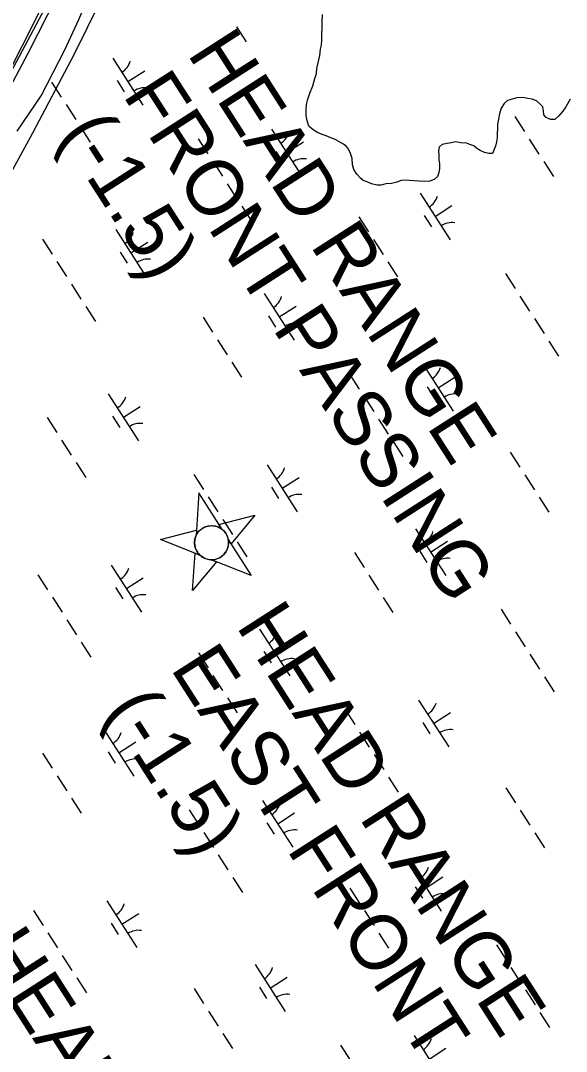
# Model space of a CAD drawing. Extents: x 3937982 to 3958556, y 219448 to 241894.
# Drawn here: x 3943922 to 3944412, y 234922 to 235847 of the extents above; entities that cross this region are included whole.
import ezdxf

# ---------------------------------------------------------------- set-up
doc = ezdxf.new("R2010")
doc.units = 0
for name, color, linetype in [('V-CHAN-NAID', 7, 'Continuous'), ('V-RIVR-EDGE', 7, 'Continuous'), ('V-RIVR-JETY', 7, 'Continuous'), ('V-RRAP-FSHR', 7, 'Continuous'), ('V-TOPO-SHOR', 7, 'Continuous'), ('V-WETL-SWMP', 7, 'Continuous')]:
    doc.layers.add(name, color=color, linetype=linetype)

msp = doc.modelspace()

# ---------------------------------------------------------------- linework, layer by layer
at = {"layer": 'V-CHAN-NAID'}
for points in [[(3944102.509, 235391.101), (3944082.065, 235423.425), (3944079.606, 235385.257), (3944080.108, 235386.241), (3944080.574, 235387.022), (3944081.179, 235387.901), (3944081.855, 235388.749), (3944082.313, 235389.26), (3944082.899, 235389.851), (3944083.441, 235390.344), (3944084.062, 235390.855), (3944084.763, 235391.37), (3944085.425, 235391.802), (3944086.326, 235392.318), (3944087.057, 235392.678), (3944088.089, 235393.109), (3944089.028, 235393.426), (3944089.985, 235393.682), (3944090.868, 235393.861), (3944091.733, 235393.984), (3944092.598, 235394.056), (3944093.616, 235394.079), (3944094.513, 235394.043), (3944095.317, 235393.965), (3944096.07, 235393.853), (3944096.986, 235393.664), (3944097.676, 235393.483), (3944098.728, 235393.138), (3944099.421, 235392.863), (3944100.327, 235392.443), (3944101.193, 235391.97), (3944101.871, 235391.547)], [(3944102.509, 235391.101), (3944099.947, 235395.152), (3944132.362, 235403.422), (3944110.999, 235377.678), (3944108.436, 235381.73), (3944108.253, 235382.549), (3944107.948, 235383.598), (3944107.586, 235384.578), (3944107.166, 235385.518), (3944106.898, 235386.04), (3944106.518, 235386.707), (3944106.052, 235387.431), (3944105.652, 235387.988), (3944105.052, 235388.736), (3944104.591, 235389.251), (3944103.947, 235389.898), (3944103.357, 235390.428), (3944102.939, 235390.772)], [(3944083.039, 235367.637), (3944047.499, 235381.771), (3944079.914, 235390.041), (3944079.606, 235385.257), (3944079.372, 235384.729), (3944078.963, 235383.645), (3944078.696, 235382.752), (3944078.46, 235381.729), (3944078.309, 235380.807), (3944078.215, 235379.883), (3944078.179, 235379.026), (3944078.197, 235378.04), (3944078.277, 235377.073), (3944078.42, 235376.1), (3944078.577, 235375.342), (3944078.794, 235374.514), (3944079.158, 235373.425), (3944079.452, 235372.703), (3944079.891, 235371.782), (3944080.263, 235371.107), (3944080.756, 235370.318), (3944081.246, 235369.629), (3944081.782, 235368.957), (3944082.427, 235368.241)], [(3944108.436, 235381.73), (3944128.88, 235349.405), (3944093.341, 235363.54), (3944094.213, 235363.559), (3944095.255, 235363.647), (3944096.115, 235363.774), (3944097.137, 235363.992), (3944098.035, 235364.245), (3944098.832, 235364.52), (3944099.775, 235364.912), (3944100.487, 235365.259), (3944101.449, 235365.803), (3944102.308, 235366.372), (3944103.191, 235367.052), (3944103.859, 235367.639), (3944104.665, 235368.448), (3944105.392, 235369.296), (3944106.023, 235370.147), (3944106.455, 235370.81), (3944106.989, 235371.751), (3944107.426, 235372.663), (3944107.814, 235373.634), (3944108.121, 235374.58), (3944108.352, 235375.484), (3944108.555, 235376.585), (3944108.678, 235377.7), (3944108.718, 235378.726), (3944108.685, 235379.826), (3944108.607, 235380.651)], [(3944093.341, 235363.54), (3944097.795, 235361.768), (3944076.432, 235336.025), (3944078.584, 235369.409), (3944083.039, 235367.637), (3944083.689, 235367.065), (3944084.36, 235366.538), (3944085.328, 235365.877), (3944086.169, 235365.386), (3944087.142, 235364.902), (3944088.122, 235364.498), (3944089.065, 235364.182), (3944089.904, 235363.956), (3944090.875, 235363.758), (3944091.79, 235363.63), (3944092.712, 235363.557)]]:
    msp.add_lwpolyline(points, close=True, dxfattribs=at)
msp.add_circle((3944093.448, 235378.81), 15.27, dxfattribs=at)
at = {"layer": 'V-RIVR-EDGE'}
msp.add_lwpolyline([(3944193.63, 236392.457), (3944193.155, 236391.169), (3944172.689, 236343.94), (3944119.949, 236234.524), (3944097.121, 236194.379), (3944079.017, 236141.639), (3944066.422, 236128.257), (3944040.446, 236067.646), (3944007.385, 235995.227), (3943991.642, 235945.636), (3943960.942, 235890.535), (3943855.463, 235692.957), (3943812.956, 235631.558), (3943768.875, 235583.541), (3943727.155, 235505.612), (3943670.48, 235374.156), (3943636.632, 235260.018), (3943585.466, 235124.626), (3943579.956, 235075.035), (3943597.274, 234983.724), (3943619.314, 234871.947)], dxfattribs=at)
at = {"layer": 'V-RIVR-JETY'}
for points in [[(3943918.966, 235747.869), (3943940.493, 235779.634), (3943961.753, 235820.78), (3943974.23, 235847.974), (3943989.155, 235882.951), (3944009.623, 235923.326), (3944029.298, 235962.932), (3944042.598, 235993.238), (3944058.298, 236027.817), (3944072.734, 236055.375), (3944088.858, 236092.29), (3944101.007, 236124.177), (3944109.06, 236142.048), (3944128.278, 236176.577), (3944154.126, 236239.551), (3944186.216, 236301.659), (3944206.653, 236339.69), (3944222.709, 236371.526), (3944236.476, 236407.692), (3944242.031, 236423.901)], [(3944205.869, 236400.408), (3944194.979, 236373.066), (3944180.859, 236339.641), (3944150.089, 236288.851), (3944127.236, 236245.38), (3944097.892, 236184.016), (3944079.325, 236139.707), (3944064.786, 236104.334), (3944042.604, 236052.647), (3944009.232, 235982.349), (3943954.976, 235869.723), (3943928.492, 235817.704), (3943901.241, 235766.865)]]:
    msp.add_lwpolyline(points, dxfattribs=at)
at = {"layer": 'V-RRAP-FSHR'}
msp.add_lwpolyline([(3943648.444, 234864.923), (3943633.272, 234943.444), (3943617.876, 235021.948), (3943622.994, 235100.327), (3943650.171, 235175.566), (3943678.906, 235250.224), (3943708.387, 235324.593), (3943738.82, 235398.878), (3943769.606, 235472.399), (3943805.37, 235543.862), (3943853.205, 235607.915), (3943894.849, 235676.646), (3943933.18, 235746.524), (3943970.3, 235817.305), (3944005.82, 235888.983), (3944041.119, 235960.773), (3944076.417, 236032.566), (3944110.874, 236104.758), (3944144.447, 236177.374), (3944176.138, 236250.819), (3944207.167, 236324.555), (3944236.607, 236398.941), (3944248.265, 236427.951)], dxfattribs=at)
at = {"layer": 'V-TOPO-SHOR'}
for points in [[(3944236.925, 235700.745), (3944233.793, 235702.185), (3944229.615, 235703.641), (3944227.195, 235705.773), (3944223.744, 235709.316), (3944220.999, 235713.551), (3944220.006, 235717.762), (3944219.732, 235723.363), (3944218.042, 235727.934), (3944216.344, 235731.805), (3944214.628, 235734.277), (3944211.857, 235736.413), (3944209.078, 235737.849), (3944204.214, 235740.363), (3944200.382, 235741.813), (3944196.208, 235743.618), (3944192.731, 235745.064), (3944188.555, 235746.868), (3944185.43, 235748.658), (3944183.005, 235750.44), (3944180.584, 235752.572), (3944179.245, 235757.137), (3944178.262, 235762.048), (3944178.321, 235766.596), (3944178.741, 235771.837), (3944179.855, 235776.722), (3944181.674, 235781.944), (3944184.209, 235788.559), (3944186.046, 235795.182), (3944187.506, 235799.71), (3944187.918, 235804.253), (3944189.767, 235811.927), (3944190.519, 235815.765), (3944191.291, 235821.352), (3944192.043, 235825.19), (3944192.452, 235829.732), (3944192.51, 235833.93), (3944192.598, 235840.576), (3944192.665, 235845.823), (3944193.104, 235852.465)], [(3944415.312, 235776.748), (3944411.369, 235769.803), (3944408.52, 235765.992), (3944404.967, 235761.841), (3944401.424, 235758.39), (3944397.576, 235758.439), (3944393.75, 235760.239), (3944391.684, 235762.717), (3944391.381, 235766.219), (3944390.727, 235769.728), (3944388.313, 235772.208), (3944384.852, 235775.053), (3944381.022, 235776.502), (3944377.184, 235777.252), (3944372.646, 235778.014), (3944367.392, 235777.733), (3944363.182, 235776.738), (3944358.967, 235775.397), (3944356.13, 235772.634), (3944353.276, 235768.474), (3944351.811, 235763.596), (3944351.047, 235758.707), (3944349.937, 235754.173), (3944349.89, 235750.675), (3944349.816, 235745.08), (3944349.776, 235741.93), (3944349.028, 235738.442), (3944348.278, 235734.605), (3944346.828, 235730.775), (3944345.393, 235727.996), (3944342.245, 235728.037), (3944338.405, 235728.786), (3944334.581, 235730.586), (3944331.11, 235732.733), (3944328.689, 235734.865), (3944325.206, 235735.958), (3944322.072, 235737.05), (3944317.18, 235737.466), (3944312.641, 235738.225), (3944308.435, 235737.58), (3944304.926, 235736.929), (3944300.365, 235735.94), (3944297.535, 235733.527), (3944297.144, 235730.384), (3944297.443, 235726.531), (3944297.382, 235721.985), (3944298.039, 235718.827), (3944297.98, 235714.278), (3944297.232, 235710.79), (3944296.136, 235707.307), (3944293.302, 235704.546), (3944289.435, 235703.196), (3944284.534, 235702.912), (3944279.287, 235702.981), (3944275.093, 235703.387), (3944270.901, 235703.792), (3944267.403, 235703.839), (3944263.551, 235703.54), (3944259.684, 235702.193), (3944254.769, 235700.858), (3944249.868, 235700.573), (3944245.655, 235699.58), (3944242.157, 235699.627), (3944236.925, 235700.745)]]:
    msp.add_lwpolyline(points, dxfattribs=at)
at = {"layer": 'V-WETL-SWMP'}
for p, q in [((3943962.314, 235901.421), (3943897.877, 235774.016)), ((3944192.453, 235829.733), (3944192.666, 235845.824)), ((3944192.666, 235845.824), (3944193.104, 235852.465)), ((3944115.772, 235841.666), (3944124.432, 235828.212)), ((3944192.043, 235825.19), (3944192.453, 235829.733)), ((3944190.518, 235815.764), (3944191.292, 235821.352)), ((3944191.292, 235821.352), (3944192.043, 235825.19)), ((3944004.791, 235813.395), (3944031.853, 235771.352)), ((3944187.917, 235804.253), (3944189.768, 235811.926)), ((3944189.768, 235811.926), (3944190.518, 235815.764)), ((3944018.322, 235792.374), (3944033.458, 235802.116)), ((3944186.047, 235795.182), (3944187.507, 235799.71)), ((3944187.507, 235799.71), (3944187.917, 235804.253)), ((3943949.925, 235791.998), (3943958.585, 235778.544)), ((3944008.587, 235793.243), (3944015.082, 235783.152)), ((3944184.21, 235788.559), (3944186.047, 235795.182)), ((3944179.855, 235776.721), (3944181.673, 235781.945)), ((3944181.673, 235781.945), (3944184.21, 235788.559)), ((3943962.915, 235771.817), (3943971.575, 235758.363)), ((3944178.321, 235766.596), (3944178.74, 235771.838)), ((3944178.74, 235771.838), (3944179.855, 235776.721)), ((3944356.13, 235772.634), (3944353.276, 235768.474)), ((3944358.966, 235775.396), (3944356.13, 235772.634)), ((3944363.182, 235776.739), (3944358.966, 235775.396)), ((3944367.393, 235777.733), (3944363.182, 235776.739)), ((3944372.645, 235778.013), (3944367.393, 235777.733)), ((3944377.183, 235777.253), (3944372.645, 235778.013)), ((3944381.021, 235776.503), (3944377.183, 235777.253)), ((3944384.851, 235775.052), (3944381.021, 235776.503)), ((3944388.312, 235772.208), (3944384.851, 235775.052)), ((3944390.728, 235769.727), (3944388.312, 235772.208)), ((3944415.311, 235776.748), (3944411.37, 235769.803)), ((3944178.261, 235762.048), (3944178.321, 235766.596)), ((3944179.245, 235757.137), (3944178.261, 235762.048)), ((3944351.812, 235763.595), (3944351.047, 235758.707)), ((3944353.276, 235768.474), (3944351.812, 235763.595)), ((3944391.381, 235766.219), (3944390.728, 235769.727)), ((3944391.684, 235762.717), (3944391.381, 235766.219)), ((3944393.751, 235760.24), (3944391.684, 235762.717)), ((3944404.967, 235761.841), (3944401.423, 235758.389)), ((3944408.521, 235765.992), (3944404.967, 235761.841)), ((3944411.37, 235769.803), (3944408.521, 235765.992)), ((3944180.584, 235752.571), (3944179.245, 235757.137)), ((3944183.005, 235750.44), (3944180.584, 235752.571)), ((3944349.938, 235754.174), (3944349.775, 235741.931)), ((3944351.047, 235758.707), (3944349.938, 235754.174)), ((3944365.487, 235761.039), (3944374.147, 235747.585)), ((3944397.575, 235758.44), (3944393.751, 235760.24)), ((3944401.423, 235758.389), (3944397.575, 235758.44)), ((3943975.905, 235751.637), (3943984.564, 235738.183)), ((3944147.357, 235749.705), (3944174.419, 235707.662)), ((3944185.43, 235748.658), (3944183.005, 235750.44)), ((3944188.555, 235746.868), (3944185.43, 235748.658)), ((3944192.73, 235745.063), (3944188.555, 235746.868)), ((3944196.209, 235743.617), (3944192.73, 235745.063)), ((3944200.383, 235741.813), (3944196.209, 235743.617)), ((3944081.492, 235741.11), (3944090.152, 235727.656)), ((3944160.888, 235728.683), (3944176.023, 235738.426)), ((3944204.213, 235740.363), (3944200.383, 235741.813)), ((3944211.857, 235736.413), (3944204.213, 235740.363)), ((3944214.628, 235734.277), (3944211.857, 235736.413)), ((3944216.344, 235731.805), (3944214.628, 235734.277)), ((3944300.366, 235735.939), (3944297.535, 235733.527)), ((3944304.927, 235736.928), (3944300.366, 235735.939)), ((3944308.434, 235737.581), (3944304.927, 235736.928)), ((3944312.641, 235738.225), (3944308.434, 235737.581)), ((3944317.179, 235737.465), (3944312.641, 235738.225)), ((3944322.072, 235737.05), (3944317.179, 235737.465)), ((3944325.206, 235735.959), (3944322.072, 235737.05)), ((3944328.69, 235734.864), (3944325.206, 235735.959)), ((3944331.111, 235732.732), (3944328.69, 235734.864)), ((3944348.279, 235734.604), (3944346.828, 235730.775)), ((3944349.029, 235738.442), (3944348.279, 235734.604)), ((3944349.775, 235741.931), (3944349.029, 235738.442)), ((3944378.477, 235740.858), (3944387.137, 235727.404)), ((3944151.153, 235729.553), (3944157.648, 235719.462)), ((3944218.042, 235727.934), (3944216.344, 235731.805)), ((3944219.731, 235723.364), (3944218.042, 235727.934)), ((3944297.535, 235733.527), (3944297.143, 235730.384)), ((3944297.143, 235730.384), (3944297.442, 235726.531)), ((3944297.442, 235726.531), (3944297.382, 235721.984)), ((3944334.581, 235730.587), (3944331.111, 235732.732)), ((3944338.405, 235728.787), (3944334.581, 235730.587)), ((3944342.244, 235728.036), (3944338.405, 235728.787)), ((3944345.392, 235727.995), (3944342.244, 235728.036)), ((3944346.828, 235730.775), (3944345.392, 235727.995)), ((3944094.482, 235720.929), (3944103.142, 235707.475)), ((3944220.007, 235717.762), (3944219.731, 235723.364)), ((3944221, 235713.551), (3944220.007, 235717.762)), ((3944297.382, 235721.984), (3944298.039, 235718.827)), ((3944298.039, 235718.827), (3944297.979, 235714.279)), ((3944391.467, 235720.677), (3944400.127, 235707.224)), ((3944223.743, 235709.316), (3944221, 235713.551)), ((3944227.195, 235705.772), (3944223.743, 235709.316)), ((3944296.137, 235707.306), (3944293.302, 235704.545)), ((3944297.233, 235710.79), (3944296.137, 235707.306)), ((3944297.979, 235714.279), (3944297.233, 235710.79)), ((3944107.471, 235700.749), (3944116.131, 235687.295)), ((3944229.615, 235703.64), (3944227.195, 235705.772)), ((3944233.794, 235702.185), (3944229.615, 235703.64)), ((3944236.924, 235700.744), (3944233.794, 235702.185)), ((3944242.157, 235699.626), (3944236.924, 235700.744)), ((3944245.655, 235699.579), (3944242.157, 235699.626)), ((3944249.867, 235700.573), (3944245.655, 235699.579)), ((3944254.768, 235700.858), (3944249.867, 235700.573)), ((3944259.684, 235702.192), (3944254.768, 235700.858)), ((3944263.55, 235703.54), (3944259.684, 235702.192)), ((3944267.403, 235703.839), (3944263.55, 235703.54)), ((3944270.901, 235703.793), (3944267.403, 235703.839)), ((3944279.287, 235702.982), (3944270.901, 235703.793)), ((3944284.534, 235702.912), (3944279.287, 235702.982)), ((3944289.436, 235703.197), (3944284.534, 235702.912)), ((3944293.302, 235704.545), (3944289.436, 235703.197)), ((3944280.486, 235692.406), (3944307.548, 235650.363)), ((3944120.461, 235680.568), (3944129.121, 235667.114)), ((3944294.017, 235671.385), (3944309.153, 235681.127)), ((3944225.62, 235671.009), (3944234.28, 235657.555)), ((3944284.282, 235672.254), (3944290.777, 235662.164)), ((3943941.624, 235651.081), (3943950.284, 235637.627)), ((3944007.489, 235659.675), (3944034.552, 235617.632)), ((3944238.61, 235650.829), (3944247.27, 235637.375)), ((3944021.021, 235638.654), (3944036.156, 235648.396)), ((3944011.285, 235639.523), (3944017.78, 235629.433)), ((3943954.614, 235630.9), (3943963.274, 235617.446)), ((3944251.6, 235630.648), (3944260.26, 235617.194)), ((3944357.187, 235620.121), (3944365.847, 235606.667)), ((3943967.604, 235610.719), (3943976.264, 235597.265)), ((3944140.619, 235602.377), (3944167.681, 235560.334)), ((3944370.177, 235599.941), (3944378.837, 235586.487)), ((3943980.594, 235590.538), (3943989.254, 235577.084)), ((3944154.15, 235581.355), (3944169.285, 235591.098)), ((3944085.753, 235580.98), (3944094.413, 235567.526)), ((3944144.415, 235582.224), (3944150.91, 235572.134)), ((3944383.167, 235579.76), (3944391.827, 235566.306)), ((3944098.742, 235560.799), (3944107.402, 235547.345)), ((3944396.156, 235559.579), (3944404.816, 235546.125)), ((3944111.732, 235540.618), (3944120.392, 235527.164)), ((3944283.185, 235538.687), (3944310.247, 235496.643)), ((3944217.32, 235530.092), (3944225.979, 235516.638)), ((3944296.716, 235517.665), (3944311.851, 235527.408)), ((3944000.751, 235512.347), (3944027.814, 235470.304)), ((3944286.981, 235518.534), (3944293.475, 235508.444)), ((3944230.309, 235509.911), (3944238.969, 235496.457)), ((3944014.283, 235491.326), (3944029.418, 235501.068)), ((3943945.885, 235490.95), (3943954.545, 235477.496)), ((3944004.547, 235492.195), (3944011.042, 235482.105)), ((3944243.299, 235489.73), (3944251.959, 235476.276)), ((3943958.875, 235470.77), (3943967.535, 235457.316)), ((3944256.289, 235469.55), (3944264.949, 235456.096)), ((3944361.448, 235459.991), (3944370.108, 235446.537)), ((3943971.865, 235450.589), (3943980.525, 235437.135)), ((3944143.317, 235448.657), (3944170.38, 235406.614)), ((3944077.452, 235440.062), (3944086.112, 235426.608)), ((3944374.438, 235439.81), (3944383.098, 235426.356)), ((3944156.848, 235427.636), (3944171.984, 235437.378)), ((3944090.442, 235419.882), (3944099.102, 235406.428)), ((3944147.113, 235428.505), (3944153.608, 235418.414)), ((3944387.428, 235419.63), (3944396.087, 235406.176)), ((3944103.432, 235399.701), (3944112.092, 235386.247)), ((3944276.446, 235391.359), (3944303.509, 235349.315)), ((3944116.422, 235379.52), (3944125.082, 235366.066)), ((3944289.978, 235370.337), (3944305.113, 235380.079)), ((3944221.58, 235369.962), (3944230.24, 235356.508)), ((3944280.242, 235371.206), (3944286.737, 235361.116)), ((3944003.45, 235358.628), (3944030.512, 235316.584)), ((3943937.585, 235350.033), (3943946.245, 235336.579)), ((3944016.981, 235337.606), (3944032.117, 235347.349)), ((3944234.57, 235349.781), (3944243.23, 235336.327)), ((3944007.246, 235338.475), (3944013.741, 235328.385)), ((3943950.575, 235329.852), (3943959.235, 235316.398)), ((3944247.56, 235329.6), (3944256.22, 235316.146)), ((3944353.147, 235319.074), (3944361.807, 235305.62)), ((3943963.565, 235309.671), (3943972.225, 235296.217)), ((3944136.579, 235301.329), (3944163.642, 235259.286)), ((3944150.11, 235280.308), (3944165.246, 235290.05)), ((3944366.137, 235298.893), (3944374.797, 235285.439)), ((3943976.555, 235289.491), (3943985.215, 235276.037)), ((3944140.375, 235281.177), (3944146.87, 235271.086)), ((3944081.713, 235279.932), (3944090.373, 235266.478)), ((3944379.127, 235278.712), (3944387.787, 235265.258)), ((3944094.703, 235259.751), (3944103.363, 235246.297)), ((3944392.117, 235258.531), (3944400.777, 235245.077)), ((3944107.693, 235239.571), (3944116.353, 235226.117)), ((3944279.145, 235237.639), (3944306.207, 235195.596)), ((3944213.28, 235229.044), (3944221.94, 235215.59)), ((3944292.676, 235216.617), (3944307.812, 235226.36)), ((3944282.941, 235217.487), (3944289.436, 235207.396)), ((3943996.712, 235211.3), (3944023.774, 235169.256)), ((3944226.27, 235208.863), (3944234.93, 235195.409)), ((3944010.243, 235190.278), (3944025.379, 235200.02)), ((3943941.846, 235189.903), (3943950.506, 235176.449)), ((3944000.508, 235191.147), (3944007.003, 235181.057)), ((3944239.26, 235188.683), (3944247.92, 235175.229)), ((3943954.836, 235169.722), (3943963.496, 235156.268)), ((3944252.25, 235168.502), (3944260.91, 235155.048)), ((3944357.408, 235158.943), (3944366.068, 235145.489)), ((3943967.826, 235149.541), (3943976.486, 235136.087)), ((3944139.278, 235147.609), (3944166.34, 235105.566)), ((3944073.413, 235139.015), (3944082.073, 235125.561)), ((3944152.809, 235126.588), (3944167.945, 235136.33)), ((3944370.398, 235138.763), (3944379.058, 235125.309)), ((3944143.074, 235127.457), (3944149.569, 235117.367)), ((3944086.403, 235118.834), (3944095.063, 235105.38)), ((3944383.388, 235118.582), (3944392.048, 235105.128)), ((3944099.393, 235098.653), (3944108.053, 235085.199)), ((3944272.407, 235090.311), (3944299.469, 235048.268)), ((3944112.383, 235078.472), (3944121.042, 235065.018)), ((3944285.938, 235069.289), (3944301.074, 235079.032)), ((3944217.541, 235068.914), (3944226.201, 235055.46)), ((3944276.203, 235070.158), (3944282.698, 235060.068)), ((3943999.411, 235057.58), (3944026.473, 235015.537)), ((3943933.546, 235048.985), (3943942.206, 235035.531)), ((3944012.942, 235036.558), (3944028.077, 235046.301)), ((3944230.531, 235048.733), (3944239.191, 235035.279)), ((3944003.207, 235037.428), (3944009.702, 235027.337)), ((3943946.535, 235028.804), (3943955.195, 235015.35)), ((3944243.521, 235028.552), (3944252.181, 235015.098)), ((3944349.108, 235018.026), (3944357.768, 235004.572)), ((3943959.525, 235008.624), (3943968.185, 234995.17)), ((3944132.54, 235000.281), (3944159.602, 234958.238)), ((3944362.098, 234997.845), (3944370.758, 234984.391)), ((3943972.515, 234988.443), (3943981.175, 234974.989)), ((3944146.071, 234979.26), (3944161.207, 234989.002)), ((3944077.674, 234978.884), (3944086.334, 234965.43)), ((3944136.336, 234980.129), (3944142.831, 234970.039)), ((3944375.088, 234977.664), (3944383.748, 234964.21)), ((3944090.664, 234958.704), (3944099.324, 234945.25)), ((3944388.078, 234957.484), (3944396.738, 234944.03)), ((3944103.654, 234938.523), (3944112.313, 234925.069)), ((3944275.106, 234936.591), (3944302.168, 234894.548)), ((3944209.241, 234927.996), (3944217.901, 234914.542)), ((3944288.637, 234915.57), (3944303.772, 234925.312))]:
    msp.add_line(p, q, dxfattribs=at)
for centre, start, end in [((3944003.572, 235815.728), 301.99668, 343.540338), ((3944033.472, 235769.276), 81.996677, 123.540335), ((3944146.137, 235752.038), 301.99668, 343.540338), ((3944176.037, 235705.586), 81.996677, 123.540335), ((3944279.267, 235694.739), 301.99668, 343.540338), ((3944309.167, 235648.287), 81.996677, 123.540335), ((3944006.27, 235662.008), 301.99668, 343.540338), ((3944036.17, 235615.556), 81.996677, 123.540335), ((3944139.399, 235604.71), 301.99668, 343.540338), ((3944169.299, 235558.258), 81.996677, 123.540335), ((3944281.965, 235541.019), 301.99668, 343.540338), ((3944311.865, 235494.568), 81.996677, 123.540335), ((3943999.532, 235514.68), 301.99668, 343.540338), ((3944029.432, 235468.228), 81.996677, 123.540335), ((3944142.098, 235450.99), 301.99668, 343.540338), ((3944171.998, 235404.538), 81.996677, 123.540335), ((3944275.227, 235393.691), 301.99668, 343.540338), ((3944305.127, 235347.24), 81.996677, 123.540335), ((3944002.231, 235360.96), 301.99668, 343.540338), ((3944032.131, 235314.509), 81.996677, 123.540335), ((3944135.36, 235303.662), 301.99668, 343.540338), ((3944165.26, 235257.21), 81.996677, 123.540335), ((3944277.926, 235239.972), 301.99668, 343.540338), ((3943995.493, 235213.632), 301.99668, 343.540338), ((3944307.826, 235193.52), 81.996677, 123.540335), ((3944025.393, 235167.181), 81.996677, 123.540335), ((3944138.059, 235149.942), 301.99668, 343.540338), ((3944167.959, 235103.49), 81.996677, 123.540335), ((3944271.188, 235092.644), 301.99668, 343.540338), ((3944301.088, 235046.192), 81.996677, 123.540335), ((3943998.191, 235059.913), 301.99668, 343.540338), ((3944028.091, 235013.461), 81.996677, 123.540335), ((3944131.321, 235002.614), 301.99668, 343.540338), ((3944161.221, 234956.162), 81.996677, 123.540335), ((3944273.886, 234938.924), 301.99668, 343.540338)]:
    msp.add_arc(centre, 17.623, start, end, dxfattribs=at)

# ---------------------------------------------------------------- texts
at = {"layer": 'V-CHAN-NAID'}
for s, p in [('HEAD RANGE', (3944070.897, 235817.65)), ('FRONT PASSING', (3944013.12, 235780.461)), ('(-1.5)', (3943955.764, 235745.209)), ('HEAD RANGE', (3944114.808, 235304.173)), ('EAST FRONT', (3944055.852, 235266.225)), ('(-1.5)', (3943996.896, 235228.276)), ('HEAD RANGE', (3943881.968, 235012.687)), ('REAR', (3943821.834, 234973.979))]:
    msp.add_text(s, height=50, rotation=302.718379, dxfattribs=at).set_placement(p)

doc.saveas('drawing.dxf')
